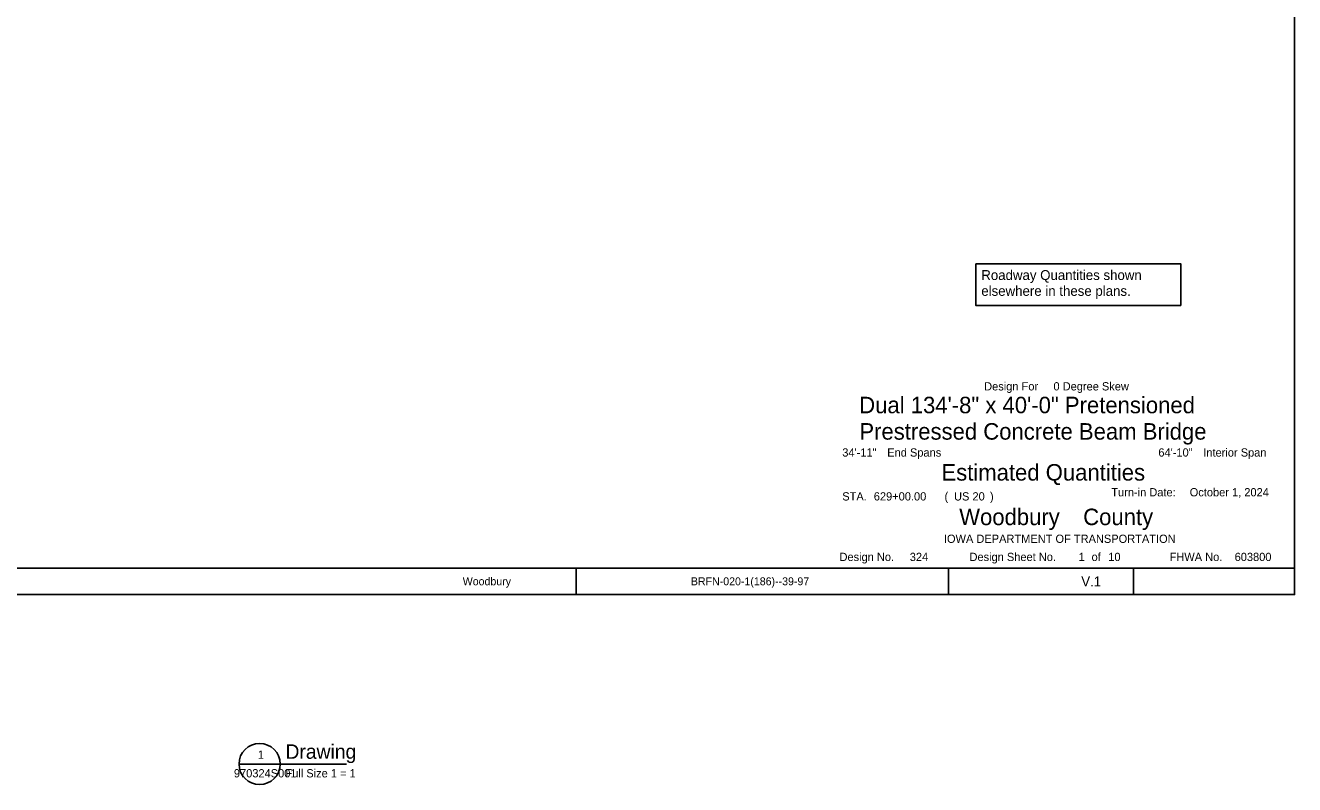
# Model space of a CAD drawing. Extents: x 0.11 to 2.72, y -0.17 to 1.89.
# Drawn here: x 1.121 to 2.723, y -0.17 to 0.788 of the extents above; entities that cross this region are included whole.
import ezdxf

# ---------------------------------------------------------------- set-up
doc = ezdxf.new("R2010")
doc.units = 0
for name, color, linetype in [('Annotation', 7, 'Continuous'), ('SheetBorder', 7, 'Continuous'), ('SheetGridMajor', 7, 'Continuous'), ('SheetText', 7, 'Continuous')]:
    doc.layers.add(name, color=color, linetype=linetype)

msp = doc.modelspace()

# ---------------------------------------------------------------- linework, layer by layer
for p, q in [((1.3904, -0.1438), (1.4425, -0.1438)), ((1.4167, -0.1438), (1.5261, -0.1438))]:
    msp.add_line(p, q)
msp.add_circle((1.4164, -0.1438), 0.026)
at = {"layer": 'SheetBorder'}
for p, q in [((0.4187, 0.1033), (1.8158, 0.1033)), ((1.8158, 0.1033), (1.8158, 0.07)), ((1.8158, 0.1033), (2.2861, 0.1033)), ((2.2861, 0.1033), (2.2861, 0.07)), ((2.2861, 0.1033), (2.5194, 0.1033)), ((2.5194, 0.1033), (2.5194, 0.07)), ((2.5194, 0.1033), (2.7229, 0.1033))]:
    msp.add_line(p, q, dxfattribs=at)
msp.add_lwpolyline([(0.1104, 1.7867), (2.7229, 1.7867), (2.7229, 0.07), (0.1104, 0.07)], close=True, dxfattribs=at)
at = {"layer": 'SheetGridMajor'}
msp.add_lwpolyline([(2.3203, 0.4877), (2.5791, 0.4877), (2.5791, 0.4351), (2.3203, 0.4351)], close=True, dxfattribs=at)

# ---------------------------------------------------------------- texts
for s, height, p in [('1', 0.0104, (1.4142, -0.1372)), ('Drawing', 0.01823, (1.449, -0.1372)), ('970324S001', 0.01042, (1.3839, -0.1607)), ('Full Size 1 = 1', 0.010417, (1.449, -0.1607))]:
    msp.add_text(s, height=height).set_placement(p)
at = {"layer": 'Annotation'}
for s, height, p in [('Design For ', 0.010417, (2.331, 0.3277)), ('0 Degree Skew', 0.010417, (2.4185, 0.3277)), ('Dual 134\'-8" x 40\'-0" Pretensioned', 0.020833, (2.1733, 0.2989)), ('Prestressed Concrete Beam Bridge', 0.020833, (2.1735, 0.2656)), ('34\'-11"', 0.01042, (2.1519, 0.2442)), (' End Spans', 0.01042, (2.2048, 0.2442)), ('64\'-10"', 0.01042, (2.5509, 0.2442)), (' Interior Span', 0.010417, (2.6038, 0.2442)), ('Estimated Quantities', 0.020833, (2.2771, 0.2139)), ('STA. ', 0.01042, (2.1519, 0.1888)), ('629+00.00', 0.01042, (2.1917, 0.1888)), ('  (', 0.01042, (2.2732, 0.1888)), ('US 20', 0.01042, (2.293, 0.1888)), (')', 0.0104, (2.3384, 0.1888)), ('Turn-in Date: ', 0.010417, (2.4915, 0.194)), ('October 1, 2024', 0.010417, (2.5905, 0.194)), ('Woodbury', 0.02083, (2.2995, 0.1577)), (' County', 0.02083, (2.4483, 0.1577)), ('IOWA DEPARTMENT OF TRANSPORTATION', 0.010417, (2.2802, 0.1353)), ('Design No. ', 0.010417, (2.1484, 0.1124)), ('324', 0.01042, (2.2371, 0.1124)), ('Design Sheet No.', 0.010417, (2.3125, 0.1124)), ('1', 0.0104, (2.4503, 0.1124)), ('of ', 0.01042, (2.4666, 0.1124)), ('10', 0.01042, (2.4877, 0.1124)), ('FHWA No. ', 0.01042, (2.5651, 0.1124)), ('603800', 0.01042, (2.6472, 0.1124))]:
    msp.add_text(s, height=height, dxfattribs=at).set_placement(p)
at = {"layer": 'SheetText'}
for s, height, p in [('Roadway Quantities shown ', 0.0125, (2.3274, 0.4671)), ('elsewhere in these plans.', 0.0125, (2.3274, 0.4471)), ('Woodbury', 0.01, (1.6728, 0.0818)), ('BRFN-020-1(186)--39-97', 0.01, (1.9608, 0.0818)), ('V.1', 0.0125, (2.4536, 0.0804))]:
    msp.add_text(s, height=height, dxfattribs=at).set_placement(p)

doc.saveas('drawing.dxf')
